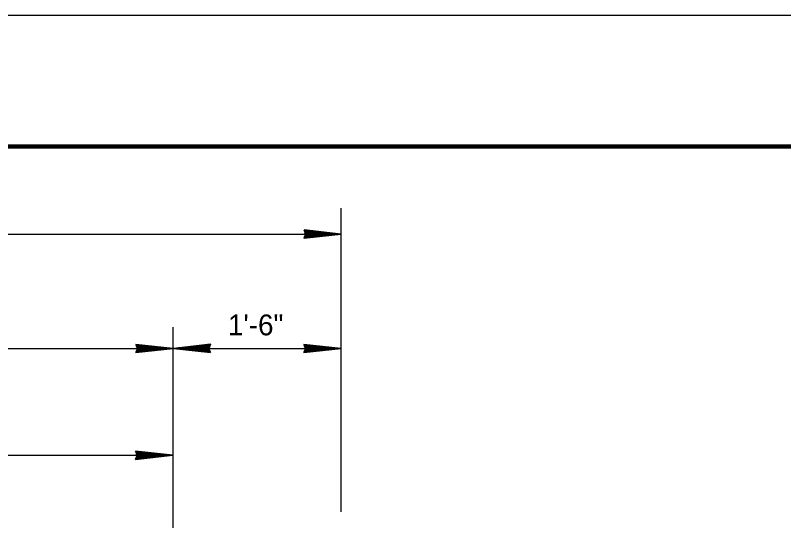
# Model space of a CAD drawing. Extents: x 1.6 to 19.9, y 2.8 to 9.5.
# Drawn here: x 17.2382 to 17.6962, y 9.2441 to 9.5451 of the extents above; entities that cross this region are included whole.
import ezdxf

# ---------------------------------------------------------------- set-up
doc = ezdxf.new("R2010")
doc.units = 0
doc.header["$LTSCALE"] = 0.0047
doc.layers.add('1', color=7, linetype='Continuous', lineweight=35)

msp = doc.modelspace()

# ---------------------------------------------------------------- linework, layer by layer
at = {"layer": '1', "lineweight": 25}
for p, q in [((19.894917, 9.545083), (16.26675, 9.545083)), ((17.432417, 9.249417), (17.432417, 9.430333)), ((16.629583, 9.414833), (17.4315, 9.414833)), ((17.33225, 9.188583), (17.33225, 9.359333)), ((16.633583, 9.34675), (17.42725, 9.34675)), ((16.730833, 9.283083), (17.332167, 9.283083))]:
    msp.add_line(p, q, dxfattribs=at)
at = {"layer": '1'}
for p, q in [((17.410667, 9.417), (17.427167, 9.415083)), ((17.410667, 9.416833), (17.427167, 9.415)), ((17.410667, 9.416833), (17.427167, 9.414917)), ((17.410667, 9.416583), (17.427167, 9.414667)), ((17.41075, 9.417083), (17.427167, 9.415167)), ((17.410333, 9.414833), (17.432417, 9.414833)), ((17.410583, 9.413417), (17.425917, 9.415083)), ((17.410667, 9.413167), (17.425917, 9.414833)), ((17.410667, 9.413), (17.426083, 9.414667)), ((17.41075, 9.41275), (17.426083, 9.414417)), ((17.310417, 9.3455), (17.325833, 9.347)), ((17.3105, 9.348917), (17.327, 9.347083)), ((17.3105, 9.348833), (17.327, 9.347)), ((17.3105, 9.34875), (17.327, 9.347)), ((17.3105, 9.348667), (17.327, 9.346833)), ((17.3105, 9.348333), (17.327, 9.346667)), ((17.354, 9.345167), (17.337667, 9.346833)), ((17.353917, 9.348833), (17.338667, 9.347167)), ((17.353917, 9.348667), (17.338667, 9.347)), ((17.354, 9.348333), (17.33875, 9.34675)), ((17.354, 9.348083), (17.33875, 9.3465)), ((17.410583, 9.348833), (17.427083, 9.347)), ((17.410583, 9.34875), (17.427083, 9.347)), ((17.410583, 9.348667), (17.427083, 9.346833)), ((17.410583, 9.348333), (17.427083, 9.346667)), ((17.410583, 9.3455), (17.425917, 9.347)), ((17.410667, 9.348917), (17.427083, 9.347083)), ((17.310083, 9.34675), (17.33225, 9.34675)), ((17.3105, 9.345167), (17.325833, 9.34675)), ((17.3105, 9.344917), (17.325917, 9.3465)), ((17.3105, 9.344583), (17.325917, 9.346417)), ((17.3545, 9.34675), (17.332417, 9.34675)), ((17.353917, 9.344583), (17.337583, 9.3465)), ((17.353917, 9.344667), (17.337583, 9.3465)), ((17.353917, 9.34475), (17.337583, 9.3465)), ((17.353917, 9.344917), (17.337667, 9.34675)), ((17.41025, 9.34675), (17.432333, 9.34675)), ((17.410583, 9.345167), (17.425917, 9.34675)), ((17.410583, 9.344917), (17.425917, 9.3465)), ((17.410667, 9.344583), (17.425917, 9.346417)), ((17.309917, 9.283083), (17.332167, 9.283083)), ((17.31025, 9.281667), (17.32575, 9.283333)), ((17.310333, 9.285167), (17.326917, 9.283333)), ((17.310333, 9.285083), (17.326917, 9.28325)), ((17.310333, 9.285), (17.326917, 9.283167)), ((17.310333, 9.28475), (17.326917, 9.282917)), ((17.310333, 9.281417), (17.32575, 9.283083)), ((17.310333, 9.281167), (17.325833, 9.282833)), ((17.310417, 9.28525), (17.326917, 9.283417)), ((17.310417, 9.280917), (17.325833, 9.282667))]:
    msp.add_line(p, q, dxfattribs=at)
at = {"layer": '1', "lineweight": 106}
msp.add_lwpolyline([(19.823, 7.367), (19.823, 9.467), (16.423, 9.467), (16.423, 7.367)], dxfattribs=at)
at = {"layer": '1'}
for points in [[(17.410333, 9.417333), (17.432417, 9.414833), (17.410333, 9.412417), (17.411333, 9.414833)], [(17.310083, 9.349083), (17.33225, 9.34675), (17.310083, 9.344333), (17.311167, 9.34675)], [(17.3545, 9.344333), (17.332417, 9.34675), (17.3545, 9.349333), (17.35325, 9.34675)], [(17.41025, 9.349083), (17.432333, 9.34675), (17.41025, 9.344333), (17.411333, 9.34675)], [(17.309917, 9.2855), (17.332167, 9.283083), (17.309917, 9.280583), (17.311083, 9.283083)]]:
    msp.add_lwpolyline(points, close=True, dxfattribs=at)
for points in [[(17.411667, 9.415083), (17.421583, 9.41525), (17.4215, 9.415), (17.419667, 9.415083), (17.411667, 9.41525), (17.418167, 9.415417), (17.4115, 9.415583), (17.416, 9.415667), (17.41125, 9.415917), (17.418833, 9.415417), (17.428583, 9.415), (17.426667, 9.414417), (17.429333, 9.414667), (17.411667, 9.414667), (17.416917, 9.414333), (17.4115, 9.414333), (17.422667, 9.415), (17.411333, 9.413833), (17.411833, 9.415), (17.410833, 9.416667), (17.411333, 9.41625), (17.411833, 9.415417), (17.412333, 9.415667), (17.411833, 9.416333), (17.411583, 9.41475), (17.411167, 9.413833), (17.41075, 9.412833)], [(17.3115, 9.347), (17.321417, 9.347167), (17.321417, 9.347), (17.3195, 9.347), (17.3115, 9.347167), (17.318, 9.347333), (17.31125, 9.3475), (17.31575, 9.347667), (17.311, 9.347917), (17.31875, 9.347333), (17.328417, 9.347), (17.3265, 9.346417), (17.32925, 9.346667), (17.3115, 9.3465), (17.316667, 9.34625), (17.31125, 9.34625), (17.3225, 9.347), (17.311083, 9.345833), (17.311583, 9.347), (17.310667, 9.3485), (17.311083, 9.348083), (17.311583, 9.347333), (17.312083, 9.347583), (17.311667, 9.34825), (17.311333, 9.34675), (17.311, 9.345833), (17.3105, 9.344667)], [(17.353, 9.3465), (17.343167, 9.346417), (17.343167, 9.346667), (17.345, 9.3465), (17.353, 9.346417), (17.346583, 9.34625), (17.35325, 9.346083), (17.348583, 9.345917), (17.353333, 9.34575), (17.345917, 9.34625), (17.336083, 9.346667), (17.338083, 9.347167), (17.3355, 9.347), (17.353, 9.347), (17.347833, 9.347333), (17.35325, 9.347333), (17.342, 9.3465), (17.35325, 9.34775), (17.352917, 9.3465), (17.35375, 9.345083), (17.35325, 9.3455), (17.352917, 9.34625), (17.35225, 9.346), (17.35275, 9.345417), (17.353, 9.346833), (17.3535, 9.34775), (17.353917, 9.348833)], [(17.411583, 9.347), (17.4215, 9.347167), (17.421417, 9.347), (17.419583, 9.347), (17.411583, 9.347167), (17.417917, 9.347333), (17.411333, 9.3475), (17.415917, 9.347667), (17.411167, 9.347917), (17.41875, 9.347333), (17.428583, 9.347), (17.426583, 9.346417), (17.42925, 9.346667), (17.411583, 9.3465), (17.416833, 9.34625), (17.411333, 9.34625), (17.422583, 9.347), (17.41125, 9.345833), (17.411667, 9.347), (17.41075, 9.3485), (17.41125, 9.348083), (17.411667, 9.347333), (17.41225, 9.347583), (17.411833, 9.34825), (17.4115, 9.34675), (17.411083, 9.345833), (17.410667, 9.344667)], [(17.311417, 9.283333), (17.321333, 9.2835), (17.32125, 9.28325), (17.319417, 9.283333), (17.311417, 9.2835), (17.317833, 9.283667), (17.311167, 9.283833), (17.31575, 9.284), (17.310917, 9.28425), (17.318583, 9.283667), (17.328417, 9.28325), (17.326417, 9.282667), (17.329167, 9.282917), (17.311417, 9.282833), (17.316583, 9.2825), (17.311167, 9.2825), (17.322417, 9.28325), (17.311, 9.282083), (17.3115, 9.28325), (17.3105, 9.284833), (17.311, 9.2845), (17.3115, 9.283667), (17.312, 9.283917), (17.311583, 9.284583), (17.31125, 9.283), (17.310833, 9.282083), (17.310417, 9.281)]]:
    msp.add_lwpolyline(points, dxfattribs=at)

# ---------------------------------------------------------------- texts
msp.add_text('1\'-6"', height=0.01242, dxfattribs=at).set_placement((17.364917, 9.3545))

doc.saveas('drawing.dxf')
